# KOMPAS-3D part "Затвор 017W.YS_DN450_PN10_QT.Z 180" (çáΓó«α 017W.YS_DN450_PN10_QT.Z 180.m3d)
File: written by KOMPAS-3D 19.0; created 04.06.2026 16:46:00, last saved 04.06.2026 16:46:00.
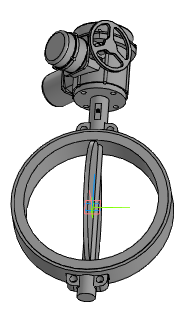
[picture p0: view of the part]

Document properties: Автор: Энергия; Полное имя файла: ..\..\..\3d для проектировщиков\017W разные\x.x Тип 017W.Y(S) Затвор дисковый поворотный межфланцевый\Затвор 017W.Y(S)_DN32-DN450_QT.Z\Затвор 017W.YS_DN450_PN10_QT.Z 180.a3d

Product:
- Part/product: Затвор 017W.YS_DN450_PN10_QT.Z 180
    Масса: 158.877

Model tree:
1. Операция без истории:1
